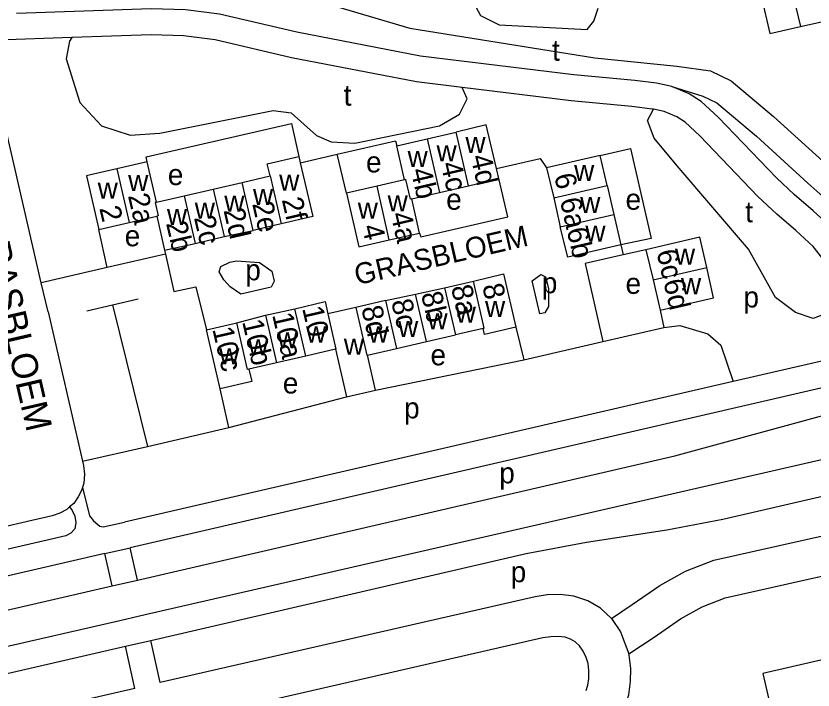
# Model space of a CAD drawing. Extents: x 155696 to 157795, y 382328 to 384028.
# Drawn here: x 157124.8 to 157277.3, y 383010.6 to 383139.6 of the extents above; entities that cross this region are included whole.
import ezdxf

# ---------------------------------------------------------------- set-up
doc = ezdxf.new("R2010")
doc.units = 0
for name, color, linetype in [('BLT_Basislijn', 7, 'Continuous'), ('BLT_Bebouwing', 7, 'Continuous'), ('BLT_Centroide', 7, 'Continuous'), ('BLT_Huisnummer', 7, 'Continuous'), ('BLT_Onderverdeling_panden', 7, 'Continuous'), ('BLT_Straatnaam', 7, 'Continuous'), ('BLT_Straatnaam_verkleind', 7, 'Continuous')]:
    doc.layers.add(name, color=color, linetype=linetype)

msp = doc.modelspace()

# ---------------------------------------------------------------- linework, layer by layer
at = {"layer": 'BLT_Basislijn'}
for p, q in [((157262.64, 383163.9), (157269.01, 383136.17)), ((157269.01, 383136.17), (157274.89, 383137.52)), ((157135.52, 383135.41), (157118.96, 383134.84)), ((157129.67, 383088.48), (157118.96, 383134.84)), ((157179.19, 383111.47), (157186.29, 383113.1)), ((157188.06, 383105.63), (157186.29, 383113.1)), ((157276.33, 383107.58), (157293.57, 383091.96)), ((157142.29, 383091.39), (157140.67, 383098.7)), ((157240.56, 383095.73), (157240.96, 383093.83)), ((157153.24, 383094.72), (157153.42, 383093.95)), ((157245.34, 383094.83), (157240.96, 383093.83)), ((157153.42, 383093.95), (157142.29, 383091.39)), ((157153.42, 383093.95), (157155.01, 383086.81)), ((157142.29, 383091.39), (157129.67, 383088.48)), ((157130.95, 383082.95), (157129.67, 383088.48)), ((157347.97, 383089.48), (157261.99, 383069.59)), ((157143.29, 383084.27), (157148.22, 383085.43)), ((157138.37, 383083.12), (157143.29, 383084.27)), ((157143.29, 383084.27), (157149.99, 383057.19)), ((157130.95, 383082.95), (157137.56, 383054.33)), ((157248.05, 383083.23), (157248.76, 383079.95)), ((157220.47, 383079.98), (157221.97, 383073.77)), ((157237.11, 383077.26), (157248.76, 383079.95)), ((157221.97, 383073.77), (157237.11, 383077.26)), ((157149.53, 383024.99), (157366.86, 383074.83)), ((157193.61, 383067.93), (157221.97, 383073.77)), ((157261.99, 383069.59), (157145.6, 383042.67)), ((157165.53, 383060.77), (157163.88, 383068.22)), ((157165.53, 383060.77), (157188.06, 383066.64)), ((157149.99, 383057.19), (157165.53, 383060.77)), ((157137.56, 383054.33), (157149.99, 383057.19)), ((157127.86, 383043), (157006.21, 383014.9)), ((157129.81, 383043.45), (157127.86, 383043)), ((157141.82, 383036.66), (157146.69, 383037.79)), ((157148.06, 383031.61), (157146.69, 383037.79)), ((157143.19, 383030.48), (157141.82, 383036.66)), ((157143.19, 383030.48), (157148.06, 383031.61)), ((157144.66, 383023.87), (157149.53, 383024.99)), ((157000.48, 382990.8), (157144.66, 383023.87)), ((157145.75, 383018.97), (157150.63, 383020.06)), ((157152.43, 383011.97), (157150.63, 383020.06)), ((157147.55, 383010.85), (157145.75, 383018.97))]:
    msp.add_line(p, q, dxfattribs=at)
msp.add_lwpolyline([(157219.89, 383149.81), (157215.36, 383147.52), (157212.51, 383144.21), (157212.26, 383142.24), (157213.7, 383139.62), (157217.27, 383137.84), (157234.11, 383136.97), (157235.38, 383138.55), (157236.21, 383141.05), (157234.84, 383144.33), (157232.22, 383147.37), (157228.65, 383149.81), (157226.3, 383150.41), (157222.81, 383150.53)], close=True, dxfattribs=at)
for points in [[(157123.54, 383146.13), (157165.71, 383144.89), (157183.5, 383142.13), (157200.18, 383137.2), (157235.58, 383131.54), (157251.21, 383129.94), (157257.67, 383129.07), (157261.63, 383127.15), (157269.74, 383120.29), (157297.41, 383095.23)], [(157250.28, 383126.07), (157247.36, 383126.69), (157243.18, 383127.21), (157231.56, 383128.31), (157202.23, 383131.88), (157178.54, 383136.45), (157163.78, 383139.88), (157157.25, 383140.71), (157150.71, 383140.93), (157124.94, 383140.05)], [(157135.52, 383135.41), (157135.09, 383134.71), (157134.44, 383131.32), (157137.06, 383122.97), (157141.16, 383118.54), (157146.65, 383116.77), (157152.31, 383117.1), (157174.04, 383121.45), (157177.44, 383121), (157179.97, 383118.78), (157182.31, 383116.65), (157185.13, 383115.46), (157189.66, 383115.21), (157205.85, 383118.56), (157209.64, 383120.77), (157211.16, 383123.69), (157210.16, 383125.88)], [(157210.16, 383125.88), (157201.46, 383126.94), (157177.5, 383131.55), (157162.9, 383134.96), (157156.85, 383135.72), (157150.71, 383135.93), (157135.52, 383135.41)], [(157246.79, 383121.7), (157246.53, 383121.75), (157242.63, 383122.24), (157231.02, 383123.34), (157210.16, 383125.88)], [(157293.57, 383091.96), (157292.16, 383091.64), (157289.91, 383090.84), (157289.08, 383090.77), (157288.21, 383090.82), (157287.51, 383091.03), (157286.96, 383091.36), (157286.38, 383092.01), (157281.02, 383098.85), (157277.32, 383102.27), (157273.69, 383105.38), (157270.28, 383108.57), (157259.14, 383120.21), (157255.91, 383123.2), (157253.6, 383124.68), (157250.28, 383126.07)], [(157250.28, 383126.07), (157256.22, 383124.22), (157258.88, 383122.93), (157266.45, 383116.53), (157276.33, 383107.58)], [(157282.29, 383089.12), (157282.95, 383085.73), (157280.15, 383082.75), (157277.29, 383081.68), (157273.95, 383082.81), (157270.1, 383085.67), (157264.96, 383094.91), (157251.3, 383110.86), (157246.89, 383116.14), (157245.6, 383119.52), (157246.79, 383121.7)], [(157282.29, 383089.12), (157277.33, 383095.45), (157274, 383098.53), (157270.36, 383101.65), (157266.76, 383105.01), (157255.63, 383116.64), (157252.84, 383119.23), (157251.27, 383120.24), (157248.79, 383121.28), (157246.79, 383121.7)], [(157149.91, 383111.65), (157149.74, 383112.59), (157177.5, 383118.98), (157178.91, 383112.67)], [(157186.29, 383113.1), (157197.4, 383115.65), (157197.65, 383114.71)], [(157236.6, 383112.88), (157242.38, 383114.2), (157246.34, 383096.95), (157240.56, 383095.73)], [(157216.73, 383110.35), (157225.12, 383112.28), (157226.3, 383110.5)], [(157202.01, 383098), (157202.24, 383097.29), (157218.93, 383101.14), (157217.18, 383108.42)], [(157167.86, 383086.3), (157165.82, 383087.7), (157164.61, 383089.06), (157163.72, 383090.59), (157163.98, 383091.58), (157165.7, 383092.43), (157167.03, 383092.72)], [(157167.03, 383092.72), (157171.43, 383092.39), (157173.74, 383090.69), (157174.21, 383088.82), (157173.65, 383087.64), (157167.86, 383086.3)], [(157240.96, 383093.83), (157233.68, 383092.18), (157237.11, 383077.26)], [(157225.02, 383082.54), (157223.55, 383088.87), (157225.2, 383090.09), (157226.14, 383089.63)], [(157226.14, 383089.63), (157226.68, 383087.39), (157226.68, 383083.95), (157225.99, 383082.76), (157225.02, 383082.54)], [(157155.01, 383086.81), (157159.24, 383087.74), (157161.25, 383079.49)], [(157349.1, 383084.61), (157146.69, 383037.79)], [(157148.06, 383031.61), (157250.83, 383055.37), (157295.59, 383067.59), (157350.09, 383080.62)], [(157248.76, 383079.95), (157251.84, 383080.29), (157257.18, 383078.7), (157259.66, 383076.56), (157261.99, 383069.59)], [(157150.63, 383020.06), (157222.39, 383036.69), (157233.99, 383038.83), (157249.3, 383041.2), (157260.04, 383043.23), (157322.95, 383057.83), (157351.93, 383064.51)], [(157238.72, 383024.27), (157242.7, 383026.9), (157247.96, 383030.58), (157252.87, 383033.31), (157258.31, 383035.41), (157336.6, 383052.98), (157353.54, 383057.05)], [(157137.56, 383054.33), (157137.75, 383053.5), (157137.96, 383051.85), (157137.83, 383050.12), (157137.57, 383049.33)], [(157137.57, 383049.33), (157137.38, 383048.75), (157136.72, 383047.5), (157135.87, 383046.28), (157135.08, 383045.59)], [(157137.57, 383049.33), (157138.9, 383043.92), (157139.64, 383042.94), (157140.46, 383042.24), (157140.88, 383041.92), (157141.52, 383041.76), (157145.6, 383042.67)], [(157135.08, 383045.59), (157134.52, 383045.09), (157133.2, 383044.38), (157131.76, 383043.9), (157129.81, 383043.45)], [(157135.08, 383045.59), (157135.6, 383044.89), (157136.05, 383043.83), (157136.25, 383042.62), (157136.05, 383041.4), (157135.34, 383040.58), (157134.34, 383040.06), (157130.78, 383039.24)], [(157242.07, 383017.47), (157246.93, 383020.68), (157251.95, 383024.19), (157256.08, 383026.48), (157260.5, 383028.19), (157338.3, 383045.66)], [(157130.78, 383039.24), (157025.33, 383014.85), (157016.25, 383013.32), (157006.67, 383012.85)], [(157141.82, 383036.66), (157026.31, 383009.94), (157016.79, 383008.34), (157007.78, 383007.9)], [(157009.64, 382999.61), (157143.19, 383030.48)], [(157228.94, 383028.82), (157226.46, 383028.76), (157224.13, 383028.42), (157152.43, 383011.97)], [(157238.72, 383024.27), (157236.67, 383026.2), (157234.23, 383027.66), (157231.56, 383028.52), (157228.94, 383028.82)], [(157238.72, 383024.27), (157240.46, 383021.7), (157242.07, 383017.47)], [(157233.87, 383010.49), (157234.23, 383011.51), (157234.4, 383012.79), (157234.42, 383014.28), (157234.28, 383015.61), (157233.91, 383016.81), (157233.33, 383018), (157232.62, 383019.02), (157231.82, 383019.78), (157230.9, 383020.32), (157229.85, 383020.66), (157228.58, 383020.81), (157227.14, 383020.77), (157225.61, 383020.55), (157025.13, 382974.57)], [(157012.23, 382988.14), (157145.75, 383018.97)], [(157230.1, 382993.44), (157239.66, 383004.69), (157241.11, 383006.96), (157242.05, 383009.63), (157242.39, 383012.22), (157242.42, 383014.65), (157242.15, 383017.21), (157242.07, 383017.47)], [(157281.29, 383016.86), (157267.69, 383013.73), (157274.62, 382983.57)], [(157147.55, 383010.85), (157022.84, 382982.25), (157019.94, 382981.18), (157017.17, 382979.67), (157014.56, 382977.64)]]:
    msp.add_lwpolyline(points, dxfattribs=at)
at = {"layer": 'BLT_Bebouwing'}
for p, q in [((157273.55, 383143.27), (157274.89, 383137.52)), ((157274.89, 383137.52), (157283.14, 383139.43)), ((157203.46, 383116.04), (157209.01, 383117.32)), ((157197.65, 383114.71), (157203.46, 383116.04)), ((157199.16, 383108.21), (157197.65, 383114.71)), ((157178.91, 383112.67), (157179.19, 383111.47)), ((157236.6, 383112.88), (157226.3, 383110.5)), ((157237.94, 383107.08), (157236.6, 383112.88)), ((157149.91, 383111.65), (157144.11, 383110.31)), ((157151.68, 383103.92), (157149.91, 383111.65)), ((157217.18, 383108.42), (157216.73, 383110.35)), ((157226.3, 383110.5), (157227.68, 383104.72)), ((157168.1, 383107.71), (157173.43, 383108.94)), ((157199.16, 383108.21), (157193.9, 383106.99)), ((157211.37, 383107.07), (157217.18, 383108.42)), ((157156.98, 383105.14), (157162.54, 383106.43)), ((157162.54, 383106.43), (157168.1, 383107.71)), ((157193.9, 383106.99), (157188.06, 383105.63)), ((157205.82, 383105.78), (157211.37, 383107.07)), ((157237.94, 383107.08), (157239.22, 383101.54)), ((157151.68, 383103.92), (157156.98, 383105.14)), ((157200.54, 383104.55), (157205.82, 383105.78)), ((157202.01, 383098), (157200.54, 383104.55)), ((157227.68, 383104.72), (157228.95, 383099.17)), ((157146.46, 383100.02), (157151.79, 383101.24)), ((157151.79, 383101.24), (157153.24, 383094.72)), ((157239.22, 383101.54), (157240.56, 383095.73)), ((157140.67, 383098.7), (157146.46, 383100.02)), ((157175.52, 383099.76), (157170.22, 383098.53)), ((157159.08, 383096.04), (157164.64, 383097.32)), ((157164.64, 383097.32), (157170.22, 383098.53)), ((157196.21, 383096.7), (157202.01, 383098)), ((157153.24, 383094.72), (157159.08, 383096.04)), ((157245.34, 383094.83), (157246.69, 383089.05)), ((157206.82, 383087.51), (157212.34, 383088.82)), ((157246.69, 383089.05), (157248.05, 383083.23)), ((157201.23, 383086.31), (157206.82, 383087.51)), ((157195.54, 383085.08), (157189.86, 383083.77)), ((157195.54, 383085.08), (157201.23, 383086.31)), ((157172.56, 383082.3), (157178.14, 383083.54)), ((157189.86, 383083.77), (157184.51, 383082.53)), ((157167.06, 383080.84), (157172.56, 383082.3)), ((157161.25, 383079.49), (157167.06, 383080.84)), ((157163.88, 383068.22), (157161.25, 383079.49)), ((157214.18, 383079.76), (157208.89, 383078.54)), ((157203.33, 383077.25), (157208.89, 383078.54)), ((157192.05, 383074.65), (157197.64, 383075.94)), ((157197.64, 383075.94), (157203.33, 383077.25)), ((157180.24, 383074.46), (157174.66, 383073.18)), ((157185.95, 383075.78), (157180.24, 383074.46)), ((157185.95, 383075.78), (157188.06, 383066.64)), ((157193.61, 383067.93), (157192.05, 383074.65)), ((157174.66, 383073.18), (157169.38, 383071.95)), ((157188.06, 383066.64), (157193.61, 383067.93))]:
    msp.add_line(p, q, dxfattribs=at)
for points in [[(157216.73, 383110.35), (157214.78, 383118.72), (157209.01, 383117.32)], [(157173.43, 383108.94), (157172.9, 383111.28), (157178.91, 383112.67)], [(157179.19, 383111.47), (157181.58, 383101.17), (157175.52, 383099.76)], [(157144.11, 383110.31), (157138.81, 383109.1), (157138.32, 383108.98), (157140.67, 383098.7)], [(157188.06, 383105.63), (157190.43, 383095.4), (157196.21, 383096.7)], [(157240.56, 383095.73), (157230.37, 383093.38), (157228.95, 383099.17)], [(157256.95, 383091.4), (157255.61, 383097.2), (157245.34, 383094.83)], [(157248.05, 383083.23), (157258.24, 383085.62), (157256.95, 383091.4)], [(157212.34, 383088.82), (157218.11, 383090.22), (157220.47, 383079.98)], [(157178.14, 383083.54), (157183.97, 383084.89), (157184.51, 383082.53)], [(157220.47, 383079.98), (157214.44, 383078.59), (157214.18, 383079.76)], [(157169.38, 383071.95), (157169.92, 383069.62), (157163.88, 383068.22)]]:
    msp.add_lwpolyline(points, dxfattribs=at)
at = {"layer": 'BLT_Onderverdeling_panden'}
for p, q in [((157211.37, 383107.07), (157209.01, 383117.32)), ((157203.46, 383116.04), (157205.82, 383105.78)), ((157144.11, 383110.31), (157146.46, 383100.02)), ((157173.43, 383108.94), (157175.52, 383099.76)), ((157162.54, 383106.43), (157164.64, 383097.32)), ((157170.22, 383098.53), (157168.1, 383107.71)), ((157196.21, 383096.7), (157193.9, 383106.99)), ((157227.68, 383104.72), (157237.94, 383107.08)), ((157156.98, 383105.14), (157159.08, 383096.04)), ((157228.95, 383099.17), (157239.22, 383101.54)), ((157246.69, 383089.05), (157256.95, 383091.4)), ((157206.82, 383087.51), (157208.89, 383078.54)), ((157195.54, 383085.08), (157197.64, 383075.94)), ((157203.33, 383077.25), (157201.23, 383086.31)), ((157180.24, 383074.46), (157178.14, 383083.54)), ((157172.56, 383082.3), (157174.66, 383073.18))]:
    msp.add_line(p, q, dxfattribs=at)
for points in [[(157200.54, 383104.55), (157200.28, 383104.48), (157199.4, 383108.26), (157199.16, 383108.21)], [(157151.68, 383103.92), (157151.44, 383103.87), (157152.03, 383101.3), (157151.79, 383101.24)], [(157214.18, 383079.76), (157214.41, 383079.81), (157212.34, 383088.82)], [(157189.86, 383083.77), (157191.97, 383074.63), (157192.05, 383074.65)], [(157184.51, 383082.53), (157186.04, 383075.8), (157185.95, 383075.78)], [(157169.38, 383071.95), (157169.11, 383071.89), (157167.06, 383080.84)]]:
    msp.add_lwpolyline(points, dxfattribs=at)

# ---------------------------------------------------------------- texts
at = {"layer": 'BLT_Centroide'}
for s, p in [('t', (157227.37, 383130.99)), ('t', (157187.5, 383122.39)), ('w', (157210.8, 383113.35)), ('w', (157205.27, 383111.74)), ('e', (157191.78, 383109.61)), ('w', (157199.73, 383110.67)), ('w', (157231.59, 383107.99)), ('e', (157153.87, 383107.19)), ('w', (157146.28, 383106.04)), ('w', (157175.17, 383106.1)), ('w', (157140.45, 383104.61)), ('w', (157170.16, 383103.4)), ('w', (157164.67, 383102.11)), ('w', (157195.91, 383102.15)), ('e', (157207.12, 383102.47)), ('w', (157232.75, 383101.83)), ('e', (157241.43, 383102.47)), ('w', (157159.02, 383100.75)), ('w', (157190.2, 383100.78)), ('t', (157264.32, 383100.07)), ('w', (157153.7, 383099.57)), ('w', (157233.74, 383096.35)), ('e', (157145.62, 383095.48)), ('w', (157250.88, 383091.97)), ('p', (157168.69, 383088.97)), ('p', (157225.41, 383086.49)), ('e', (157241.43, 383086.37)), ('w', (157252.03, 383086.31)), ('p', (157263.99, 383083.77)), ('w', (157214.55, 383081.96)), ('w', (157208.94, 383080.84)), ('w', (157203.53, 383079.58)), ('w', (157197.91, 383078.11)), ('w', (157174.83, 383075.93)), ('w', (157180.31, 383077.06)), ('w', (157192.23, 383077.06)), ('w', (157169.23, 383074.62)), ('w', (157187.54, 383074.71)), ('w', (157163.69, 383072.89)), ('e', (157204.12, 383072.7)), ('e', (157175.87, 383067.3)), ('p', (157199.07, 383062.54)), ('p', (157217.27, 383050.11)), ('p', (157219.46, 383031.19))]:
    msp.add_text(s, height=4, dxfattribs=at).set_placement(p)
at = {"layer": 'BLT_Huisnummer'}
for s, p in [('4d', (157211.76, 383112.63)), ('4c', (157206.05, 383111.25)), ('4b', (157200.3, 383110.04)), ('6', (157227.75, 383109.01)), ('2a', (157146.22, 383105.18)), ('2f', (157175.65, 383104.42)), ('2e', (157169.99, 383103.62)), ('6a', (157228.83, 383104.35)), ('2', (157140.75, 383102.77)), ('2d', (157164.5, 383102.37)), ('4a', (157196.46, 383101.64)), ('2b', (157153.51, 383099.88)), ('2c', (157158.85, 383100.96)), ('4', (157190.99, 383099.25)), ('6b', (157230.14, 383098.66)), ('6c', (157247.32, 383094.45)), ('8a', (157208.02, 383087.66)), ('8', (157213.99, 383087.91)), ('6d', (157248.63, 383088.78)), ('8b', (157202.28, 383086.37)), ('8c', (157196.58, 383084.94)), ('10', (157179.55, 383083.61)), ('8d', (157190.85, 383083.67)), ('10a', (157173.81, 383082.36)), ('10b', (157168.07, 383081.07)), ('10c', (157162.37, 383079.64))]:
    msp.add_text(s, height=4, rotation=283.0104, dxfattribs=at).set_placement(p)
at = {"layer": 'BLT_Straatnaam'}
msp.add_text('GRASBLOEM', height=5, rotation=283.0063, dxfattribs=at).set_placement((157117.41, 383100.99))
at = {"layer": 'BLT_Straatnaam_verkleind'}
msp.add_text('GRASBLOEM', height=4, rotation=13.0063, dxfattribs=at).set_placement((157190.06, 383088.02))

doc.saveas('drawing.dxf')
